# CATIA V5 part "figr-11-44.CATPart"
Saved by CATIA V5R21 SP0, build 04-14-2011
Part number: Part1
Bounding box of the stored display mesh (mm): x -59 to 59, y -60 to 60, z 0 to 39.8
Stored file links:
  D:\CATIA V5R21 E-RESOURCES\CATIA-V5R21\catia-v5r21-prt\c11-catia-v5r21-prt\c11-catia-v5r21-figr-11-44.CATPart
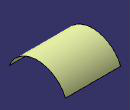
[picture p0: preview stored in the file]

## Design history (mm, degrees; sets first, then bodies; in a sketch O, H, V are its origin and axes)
AxisSystem1: origin (0, 0, 0), X (1, 0, 0), Y (0, 1, 0), Z (0, 0, 1)
AxisSystem2: origin (0, 150, -30), X (1, 0, 0), Y (0, 1, 0), Z (0, 0, 1)
Set1
  Extrude1: Element1 Sketch2, Lim1 59, Lim2 59, Direction yz-plane
  Sketch1 on yz-plane, origin (0, 0, 0), H (0, 1, 0), V (0, 0, 1)
    point P1 (150, -30)
  AxisToAxis1: ToTransfor Extrude1, AxisOrigin AxisSystem1, Axis AxisSystem2
Body1 (main body)
  Sketch2 on yz-plane, origin (0, 0, 0), H (0, 1, 0), V (0, 0, 1)
    arc A1 centre (0, -25) radius 65 from (-60, 0) to (60, 0) cw
    point P2 (-60, 0)
    point P3 (60, 0)
    coincidence: P2 H, P3 H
